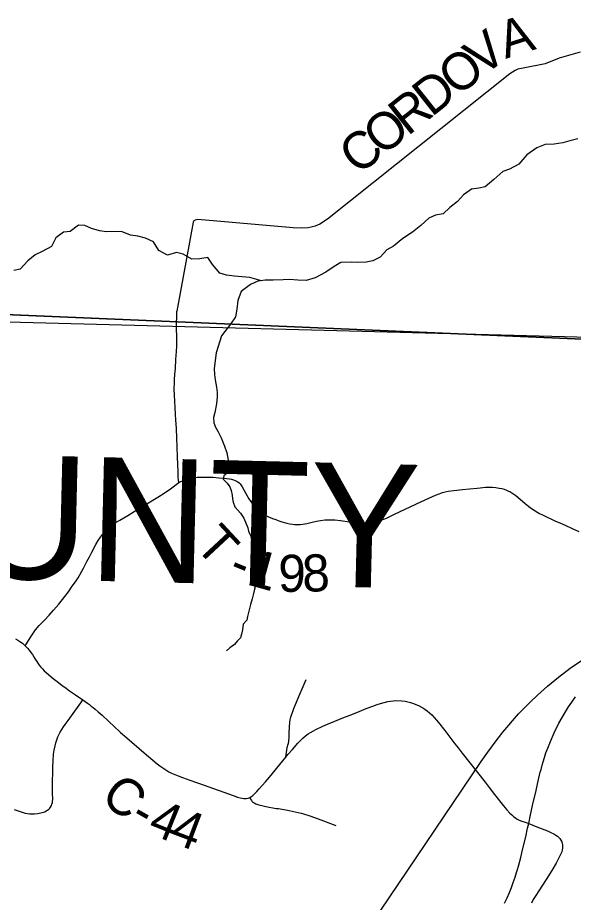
# Model space of a CAD drawing. Extents: x -1.2 to 34, y -8.5 to 22.
# Drawn here: x 4.454 to 5.304, y 16.749 to 18.102 of the extents above; entities that cross this region are included whole.
import ezdxf

# ---------------------------------------------------------------- set-up
doc = ezdxf.new("R2010")
doc.units = 0
for name, color, linetype in [('DV_X_County_Line', 7, 'Continuous'), ('GM_X_County_Road', 7, 'Continuous'), ('GM_X_County_Road_Text', 7, 'Continuous'), ('GM_X_County_Text', 7, 'Continuous'), ('GM_X_Minor_River', 7, 'Continuous'), ('GM_X_Rail_Line', 7, 'Continuous'), ('GM_X_State_Route', 7, 'Continuous'), ('GM_X_Township_Road', 7, 'Continuous'), ('GM_X_Township_Road_Text', 7, 'Continuous'), ('GM_X_Unincorporated_Text', 7, 'Continuous'), ('SH_Cut_Line', 7, 'Continuous')]:
    doc.layers.add(name, color=color, linetype=linetype)

msp = doc.modelspace()

# ---------------------------------------------------------------- linework, layer by layer
at = {"layer": 'DV_X_County_Line'}
msp.add_lwpolyline([(2.4258, 17.6899), (5.4446, 17.6102), (5.4511, 17.7337), (6.5684, 17.7149)], dxfattribs=at)
at = {"layer": 'GM_X_County_Road'}
for points in [[(4.4505, 17.1517), (4.4541, 17.1496), (4.4571, 17.1476), (4.4608, 17.1449), (4.4629, 17.1432), (4.465, 17.1412), (4.4667, 17.1396), (4.4688, 17.1374), (4.4713, 17.1344), (4.4738, 17.131), (4.4762, 17.1276), (4.4789, 17.1233), (4.4805, 17.1207), (4.4828, 17.1172), (4.4846, 17.1143), (4.4866, 17.1115), (4.4893, 17.1082), (4.4914, 17.1058), (4.4944, 17.1027), (4.4972, 17.1), (4.5012, 17.0966), (4.5079, 17.0912), (4.514, 17.0863), (4.5211, 17.0809), (4.5276, 17.0761), (4.5331, 17.0722), (4.5423, 17.0658), (4.5532, 17.0581), (4.5604, 17.0532), (4.5634, 17.0511), (4.5661, 17.0489), (4.5691, 17.0466), (4.5722, 17.0441), (4.5769, 17.04), (4.5828, 17.0347), (4.5926, 17.0259), (4.6024, 17.0166), (4.6089, 17.0106), (4.6112, 17.0085), (4.6208, 17.0003), (4.6474, 16.9774), (4.6673, 16.9603), (4.6711, 16.9572), (4.6755, 16.9541), (4.6803, 16.951), (4.6847, 16.9484), (4.689, 16.9462), (4.6941, 16.944), (4.6991, 16.9419), (4.7057, 16.9396), (4.717, 16.9356), (4.7388, 16.928), (4.7832, 16.9117), (4.7899, 16.9094), (4.7941, 16.9082), (4.7972, 16.9077), (4.7997, 16.9075), (4.8031, 16.9076), (4.8061, 16.9081), (4.8077, 16.9085), (4.8086, 16.9089)], [(4.8086, 16.9089), (4.81, 16.9096), (4.8118, 16.9108), (4.8134, 16.9121), (4.8196, 16.9182), (4.8231, 16.922), (4.8326, 16.9328), (4.8387, 16.94), (4.8593, 16.9651), (4.8639, 16.9707), (4.8672, 16.9746), (4.8739, 16.9825), (4.8824, 16.9922), (4.8848, 16.9946), (4.8902, 16.9995), (4.8941, 17.003), (4.8983, 17.0062), (4.9017, 17.0084), (4.9064, 17.0111), (4.91, 17.013), (4.9208, 17.0181), (4.9275, 17.021), (4.9387, 17.0255), (4.9514, 17.0306), (4.9609, 17.0344), (4.9675, 17.0371), (4.9762, 17.0405), (4.9871, 17.0449), (4.9972, 17.0487), (5.0039, 17.0512), (5.0088, 17.0528), (5.0144, 17.0544), (5.0198, 17.0556), (5.0239, 17.0563), (5.0281, 17.0568), (5.032, 17.0571), (5.0416, 17.0567), (5.0463, 17.0562), (5.0507, 17.0554), (5.0546, 17.0544), (5.0595, 17.0528), (5.063, 17.0514), (5.0669, 17.0496), (5.0735, 17.0461), (5.0764, 17.0443), (5.0802, 17.0415), (5.0839, 17.0384), (5.0871, 17.0353), (5.0908, 17.0315), (5.0945, 17.0274), (5.0974, 17.0239), (5.1074, 17.0112), (5.1149, 17.0013), (5.1227, 16.9912), (5.1275, 16.9847), (5.1337, 16.9766), (5.1687, 16.9325), (5.175, 16.9242), (5.1832, 16.9136), (5.1969, 16.8961), (5.2022, 16.8898), (5.2068, 16.885), (5.2095, 16.8823), (5.2128, 16.8794), (5.2152, 16.8777), (5.2179, 16.8759), (5.2209, 16.8744), (5.225, 16.8727), (5.23, 16.8709), (5.2356, 16.8689)], [(4.8086, 16.9089), (4.8101, 16.9061), (4.8113, 16.9042), (4.8121, 16.9032), (4.8135, 16.902), (4.8157, 16.9006), (4.8182, 16.8994), (4.8226, 16.8979), (4.8293, 16.8961), (4.8333, 16.8952), (4.8493, 16.8922), (4.8527, 16.8918), (4.8663, 16.8897), (4.8688, 16.8892), (4.8875, 16.885), (4.891, 16.884), (4.9009, 16.8807), (4.9135, 16.8762), (4.9405, 16.8658)], [(5.2356, 16.8689), (5.248, 16.8641), (5.2562, 16.861), (5.2641, 16.8577), (5.2695, 16.8553), (5.274, 16.8533), (5.277, 16.8515), (5.2795, 16.8497), (5.2817, 16.8478), (5.2833, 16.8459), (5.2847, 16.8438), (5.2861, 16.841), (5.2868, 16.8386), (5.2874, 16.8363), (5.2875, 16.8349), (5.2874, 16.8314), (5.2869, 16.8286), (5.286, 16.8255), (5.2843, 16.8217), (5.2824, 16.8177), (5.2802, 16.8135), (5.2775, 16.8086), (5.2708, 16.7972), (5.2622, 16.7834), (5.2512, 16.7661), (5.2466, 16.759), (5.2426, 16.7527), (5.2396, 16.7471)]]:
    msp.add_lwpolyline(points, dxfattribs=at)
at = {"layer": 'GM_X_Minor_River'}
for points in [[(5.3109, 17.9168), (5.2984, 17.9136), (5.2878, 17.9105), (5.2745, 17.9089), (5.2608, 17.9084), (5.248, 17.903), (5.2329, 17.8922), (5.2205, 17.878), (5.2061, 17.8703), (5.1959, 17.8668), (5.1823, 17.8546), (5.1691, 17.8434), (5.1592, 17.8414), (5.1479, 17.8398), (5.1358, 17.831), (5.1267, 17.821), (5.115, 17.8115), (5.1045, 17.8019)], [(5.1045, 17.8019), (5.0931, 17.7999), (5.0825, 17.7952), (5.0705, 17.7841), (5.0576, 17.7741), (5.0429, 17.7641), (5.0286, 17.7526), (5.0187, 17.7468), (5.0082, 17.7357), (4.9972, 17.7299), (4.987, 17.7283), (4.9733, 17.7278), (4.9638, 17.7281), (4.9482, 17.7276), (4.9377, 17.7215), (4.9252, 17.713), (4.9086, 17.7041), (4.8953, 17.6998), (4.8824, 17.7005), (4.8695, 17.7015), (4.8596, 17.701), (4.8448, 17.7005), (4.8322, 17.7004), (4.8209, 17.6988), (4.8099, 17.6938), (4.7955, 17.6834), (4.7903, 17.6693), (4.7889, 17.6564), (4.7871, 17.6446), (4.7791, 17.633)], [(4.8266, 17.6996), (4.809, 17.7048), (4.7965, 17.7058), (4.7855, 17.7069), (4.7733, 17.7083), (4.763, 17.7112), (4.7519, 17.7244), (4.7446, 17.7353), (4.7321, 17.733), (4.7203, 17.7325), (4.7066, 17.7403), (4.6967, 17.7429), (4.683, 17.7386), (4.6697, 17.7457), (4.6616, 17.7593), (4.649, 17.7649), (4.6376, 17.7678), (4.6262, 17.7696), (4.6125, 17.7748), (4.5893, 17.7746), (4.579, 17.7761), (4.5665, 17.7797), (4.5562, 17.7842), (4.5467, 17.7845), (4.5342, 17.7749), (4.524, 17.7741), (4.5119, 17.7652), (4.5052, 17.7523), (4.4912, 17.7445), (4.4806, 17.7391), (4.4693, 17.7303), (4.4572, 17.7173), (4.4477, 17.7153)], [(4.7791, 17.633), (4.7657, 17.6155), (4.7574, 17.5894), (4.7542, 17.5655), (4.7547, 17.556), (4.756, 17.548), (4.758, 17.537), (4.7589, 17.5286), (4.759, 17.5218), (4.758, 17.5111), (4.7555, 17.4981), (4.7534, 17.4904), (4.7539, 17.4824), (4.7562, 17.4756), (4.7605, 17.4685), (4.7648, 17.4594), (4.7699, 17.4465), (4.7735, 17.4363), (4.7755, 17.4253), (4.7779, 17.4173), (4.7791, 17.4124), (4.7765, 17.407), (4.769, 17.4012), (4.768, 17.3958), (4.7741, 17.3898), (4.778, 17.3842), (4.7803, 17.3785), (4.782, 17.3713), (4.7824, 17.366), (4.7832, 17.3606), (4.786, 17.3538), (4.7945, 17.344), (4.7995, 17.3361), (4.8058, 17.3214), (4.8066, 17.3164), (4.8105, 17.3089), (4.8113, 17.3024), (4.8153, 17.2918), (4.8177, 17.2823), (4.8193, 17.2747), (4.8198, 17.269), (4.82, 17.2511), (4.8205, 17.2454), (4.8187, 17.2366), (4.8162, 17.2278), (4.8144, 17.221), (4.8122, 17.2129), (4.8097, 17.2041), (4.8054, 17.1858), (4.8044, 17.1801), (4.7984, 17.1743), (4.7974, 17.1655), (4.796, 17.1586), (4.7945, 17.1533), (4.7897, 17.1479), (4.7856, 17.1428), (4.7785, 17.1378), (4.7732, 17.1331)]]:
    msp.add_lwpolyline(points, dxfattribs=at)
at = {"layer": 'GM_X_Rail_Line'}
msp.add_lwpolyline([(4.9954, 16.716), (5.0631, 16.8167), (5.1628, 16.9642), (5.1728, 16.9785), (5.1841, 16.9935), (5.1962, 17.0091), (5.2199, 17.0367), (5.2376, 17.0546), (5.2491, 17.0656), (5.2644, 17.0791), (5.281, 17.093), (5.2989, 17.1066), (5.3179, 17.1196)], dxfattribs=at)
at = {"layer": 'GM_X_State_Route'}
msp.add_lwpolyline([(5.1987, 16.7471), (5.2026, 16.7551), (5.2063, 16.7637), (5.2094, 16.7713), (5.212, 16.779), (5.2147, 16.7869), (5.2171, 16.794), (5.2186, 16.7988), (5.2199, 16.8036), (5.2233, 16.817), (5.2261, 16.8287), (5.2309, 16.8489), (5.2339, 16.8618), (5.2356, 16.8689), (5.2385, 16.8823), (5.2425, 16.9011), (5.2462, 16.917), (5.2496, 16.9316), (5.2533, 16.9475), (5.2544, 16.9519), (5.2562, 16.9584), (5.2577, 16.9637), (5.2597, 16.9703), (5.262, 16.9771), (5.2647, 16.9843), (5.2687, 16.9945), (5.2744, 17.008), (5.2816, 17.0224), (5.2867, 17.0315), (5.2918, 17.0398), (5.2964, 17.0474), (5.3013, 17.055), (5.307, 17.063)], dxfattribs=at)
at = {"layer": 'GM_X_Township_Road'}
for points in [[(5.3145, 18.0496), (5.2822, 18.0402), (5.2607, 18.0315), (5.2273, 18.0252), (5.2189, 18.0232), (5.215, 18.0215), (5.2068, 18.0161), (4.9279, 17.7941), (4.9159, 17.7862), (4.909, 17.7833), (4.9029, 17.7818), (4.8983, 17.7807), (4.8882, 17.7801), (4.8752, 17.7806), (4.7294, 17.7934), (4.7274, 17.7931), (4.7253, 17.7925), (4.7233, 17.7911), (4.7222, 17.7895), (4.697, 17.6531)], [(4.7001, 17.3907), (4.6997, 17.3951), (4.6994, 17.3983), (4.6991, 17.4033), (4.699, 17.4075), (4.6981, 17.4302), (4.6977, 17.4455), (4.6972, 17.4588), (4.6965, 17.4737), (4.6958, 17.487), (4.6953, 17.4949), (4.6946, 17.5056), (4.6939, 17.5151), (4.6934, 17.5251), (4.6932, 17.5336), (4.6934, 17.544), (4.6936, 17.5487), (4.6942, 17.556), (4.6949, 17.5652), (4.6958, 17.5794), (4.6967, 17.5916), (4.697, 17.5995), (4.6971, 17.607), (4.697, 17.6141), (4.6967, 17.6261), (4.697, 17.6531)], [(4.465, 17.1412), (4.467, 17.1442), (4.4701, 17.149), (4.4756, 17.1579), (4.4809, 17.1655), (4.4863, 17.172), (4.4945, 17.1805), (4.5016, 17.1878), (4.5086, 17.1956), (4.5165, 17.2049), (4.5256, 17.2164), (4.5312, 17.2235), (4.5372, 17.2323), (4.5423, 17.2389), (4.5463, 17.2448), (4.5542, 17.2598), (4.5595, 17.2699), (4.5633, 17.2771), (4.5672, 17.2844), (4.573, 17.2958), (4.5768, 17.3021), (4.5802, 17.3074), (4.5832, 17.3116), (4.5864, 17.3156), (4.5895, 17.3189), (4.5928, 17.322), (4.5956, 17.3243), (4.5991, 17.3267), (4.6029, 17.329), (4.6099, 17.3334), (4.6221, 17.3406), (4.6317, 17.3463), (4.668, 17.3683), (4.6777, 17.3748), (4.6876, 17.3814), (4.7001, 17.3907), (4.7018, 17.3917), (4.7046, 17.3932), (4.7081, 17.3947), (4.712, 17.3962), (4.7159, 17.3973), (4.7199, 17.3982), (4.7242, 17.3988), (4.7285, 17.3991), (4.7529, 17.3989), (4.7612, 17.3982), (4.7683, 17.3976), (4.7734, 17.3972), (4.7775, 17.3966), (4.7807, 17.396), (4.7839, 17.3952), (4.7864, 17.3942), (4.7887, 17.3931), (4.7907, 17.3919), (4.7926, 17.3903), (4.794, 17.389), (4.7972, 17.3842), (4.7996, 17.3797), (4.8027, 17.3742), (4.8073, 17.3659), (4.8138, 17.3567), (4.8186, 17.3511), (4.8221, 17.3474), (4.826, 17.3445), (4.8321, 17.341), (4.8376, 17.3382), (4.8437, 17.3358), (4.8485, 17.3341), (4.8531, 17.3324), (4.8578, 17.3308), (4.8654, 17.3287), (4.8698, 17.3278), (4.8739, 17.3271), (4.8774, 17.3266), (4.8813, 17.3265), (4.8858, 17.3267), (4.8899, 17.3272), (4.8962, 17.3284), (4.904, 17.33), (4.911, 17.3316), (4.9169, 17.3329), (4.9236, 17.3338), (4.9389, 17.3336), (4.9476, 17.3327), (4.9614, 17.3305), (4.972, 17.3289), (4.9754, 17.3285), (4.9791, 17.3283), (4.9889, 17.3287), (4.9928, 17.3291), (4.9939, 17.3293), (4.9973, 17.3299), (5.0011, 17.3308), (5.0044, 17.3317), (5.0099, 17.3332), (5.0152, 17.3352), (5.0178, 17.3363), (5.0304, 17.3423), (5.0705, 17.3615), (5.0828, 17.3672), (5.0928, 17.3715), (5.0984, 17.3737), (5.1034, 17.3754), (5.1078, 17.3766), (5.1123, 17.3776), (5.1212, 17.3788), (5.1341, 17.3802), (5.145, 17.3814), (5.1569, 17.3825), (5.1613, 17.383), (5.1693, 17.3837), (5.1741, 17.3838), (5.1799, 17.3836), (5.1854, 17.3832), (5.1901, 17.3825), (5.1943, 17.3817), (5.198, 17.3807), (5.2018, 17.3793), (5.2048, 17.3778), (5.2066, 17.3769), (5.2144, 17.3719), (5.216, 17.3708), (5.2258, 17.3623), (5.2299, 17.3586), (5.235, 17.3545), (5.2383, 17.352), (5.2437, 17.3486), (5.2497, 17.3449), (5.2519, 17.3435), (5.2567, 17.3412), (5.263, 17.3382), (5.2695, 17.3352), (5.2768, 17.332), (5.2834, 17.329), (5.2878, 17.327), (5.2913, 17.3254), (5.3023, 17.3205), (5.3122, 17.3161)], [(4.8639, 16.9707), (4.8656, 16.9815), (4.8662, 16.9855), (4.8675, 16.9906), (4.8679, 16.9922), (4.8684, 16.9944), (4.8686, 16.9962), (4.8689, 16.9996), (4.8691, 17.0033), (4.8692, 17.01), (4.8695, 17.0146), (4.8697, 17.0192), (4.8699, 17.0214), (4.8702, 17.0243), (4.8707, 17.0277), (4.8716, 17.032), (4.8761, 17.0452), (4.8786, 17.0513), (4.8852, 17.0668), (4.8889, 17.0754), (4.895, 17.0894)], [(4.4485, 16.8904), (4.4546, 16.8883), (4.4605, 16.8862), (4.4652, 16.8849), (4.4689, 16.8843), (4.4721, 16.884), (4.4754, 16.8839), (4.4792, 16.884), (4.4842, 16.8846), (4.4892, 16.8855), (4.4931, 16.8865), (4.495, 16.8872), (4.4972, 16.8883), (4.4992, 16.8896), (4.5012, 16.8912), (4.5028, 16.8928), (4.5038, 16.8941), (4.5052, 16.8966), (4.5061, 16.8986), (4.5067, 16.901), (4.5071, 16.9033), (4.5072, 16.9056), (4.5071, 16.9162), (4.507, 16.9291), (4.5071, 16.9351), (4.5073, 16.9459), (4.5076, 16.9585), (4.5078, 16.9632), (4.508, 16.9682), (4.5083, 16.9721), (4.5086, 16.9752), (4.5095, 16.9812), (4.5109, 16.9882), (4.512, 16.9925), (4.5134, 16.9971), (4.5153, 17.0019), (4.5189, 17.0091), (4.5236, 17.0168), (4.5265, 17.0208), (4.5308, 17.0268), (4.5387, 17.0376), (4.5479, 17.0503), (4.5503, 17.0537), (4.5532, 17.0581)]]:
    msp.add_lwpolyline(points, dxfattribs=at)
at = {"layer": 'GM_X_Unincorporated_Text'}
for p, q in [((4.6867, 17.6371), (4.4093, 17.6489)), ((5.3422, 17.6091), (4.6867, 17.6371))]:
    msp.add_line(p, q, dxfattribs=at)
msp.add_lwpolyline([(4.4093, 17.6489), (4.6867, 17.6371), (5.3422, 17.6091), (5.4446, 17.6102), (5.4511, 17.7337), (5.9208, 17.7258), (6.1864, 17.7242), (6.3301, 17.7233), (6.5687, 17.7221)], dxfattribs=at)
at = {"layer": 'SH_Cut_Line'}
for points in [[(6.5687, 17.7221), (6.3301, 17.7233), (6.1864, 17.7242), (5.9208, 17.7258), (5.4511, 17.7337), (5.4446, 17.6102), (5.3422, 17.6091), (4.6867, 17.6371), (4.4093, 17.6489)], [(4.4093, 17.6489), (4.6867, 17.6371), (5.3422, 17.6091), (5.4446, 17.6102), (5.4511, 17.7337), (5.9208, 17.7258), (6.1864, 17.7242), (6.3301, 17.7233), (6.5687, 17.7221)]]:
    msp.add_lwpolyline(points, dxfattribs=at)

# ---------------------------------------------------------------- texts
at = {"layer": 'GM_X_County_Road_Text'}
for s, rotation, p in [('C', 320.8111, (4.5783, 16.9058)), ('4', 338.0023, (4.6506, 16.8553)), ('-', 330.1136, (4.6227, 16.8706)), ('4', 339.2912, (4.6844, 16.8416))]:
    msp.add_text(s, height=0.0568, rotation=rotation, dxfattribs=at).set_placement(p)
at = {"layer": 'GM_X_County_Text'}
msp.add_text('HARRISON COUNTY', height=0.189394, rotation=358.6005, dxfattribs=at).set_placement((2.591, 17.2889))
at = {"layer": 'GM_X_Township_Road_Text'}
for s, rotation, p in [('A', 17.6407, (5.2001, 18.0391)), ('V', 37.3413, (5.1649, 18.0112)), ('O', 38.4365, (5.126, 17.9802)), ('D', 38.4455, (5.0868, 17.9492)), ('R', 38.4454, (5.0503, 17.9201)), ('O', 38.4445, (5.0111, 17.8891)), ('C', 38.4462, (4.9746, 17.86)), ('T', 312.9085, (4.723, 17.293)), ('1', 344.5113, (4.8023, 17.2354)), ('9', 359.3184, (4.8519, 17.2238)), ('8', 2.1213, (4.8899, 17.2234)), ('-', 337.4934, (4.7736, 17.2468))]:
    msp.add_text(s, height=0.0568, rotation=rotation, dxfattribs=at).set_placement(p)

doc.saveas('drawing.dxf')
